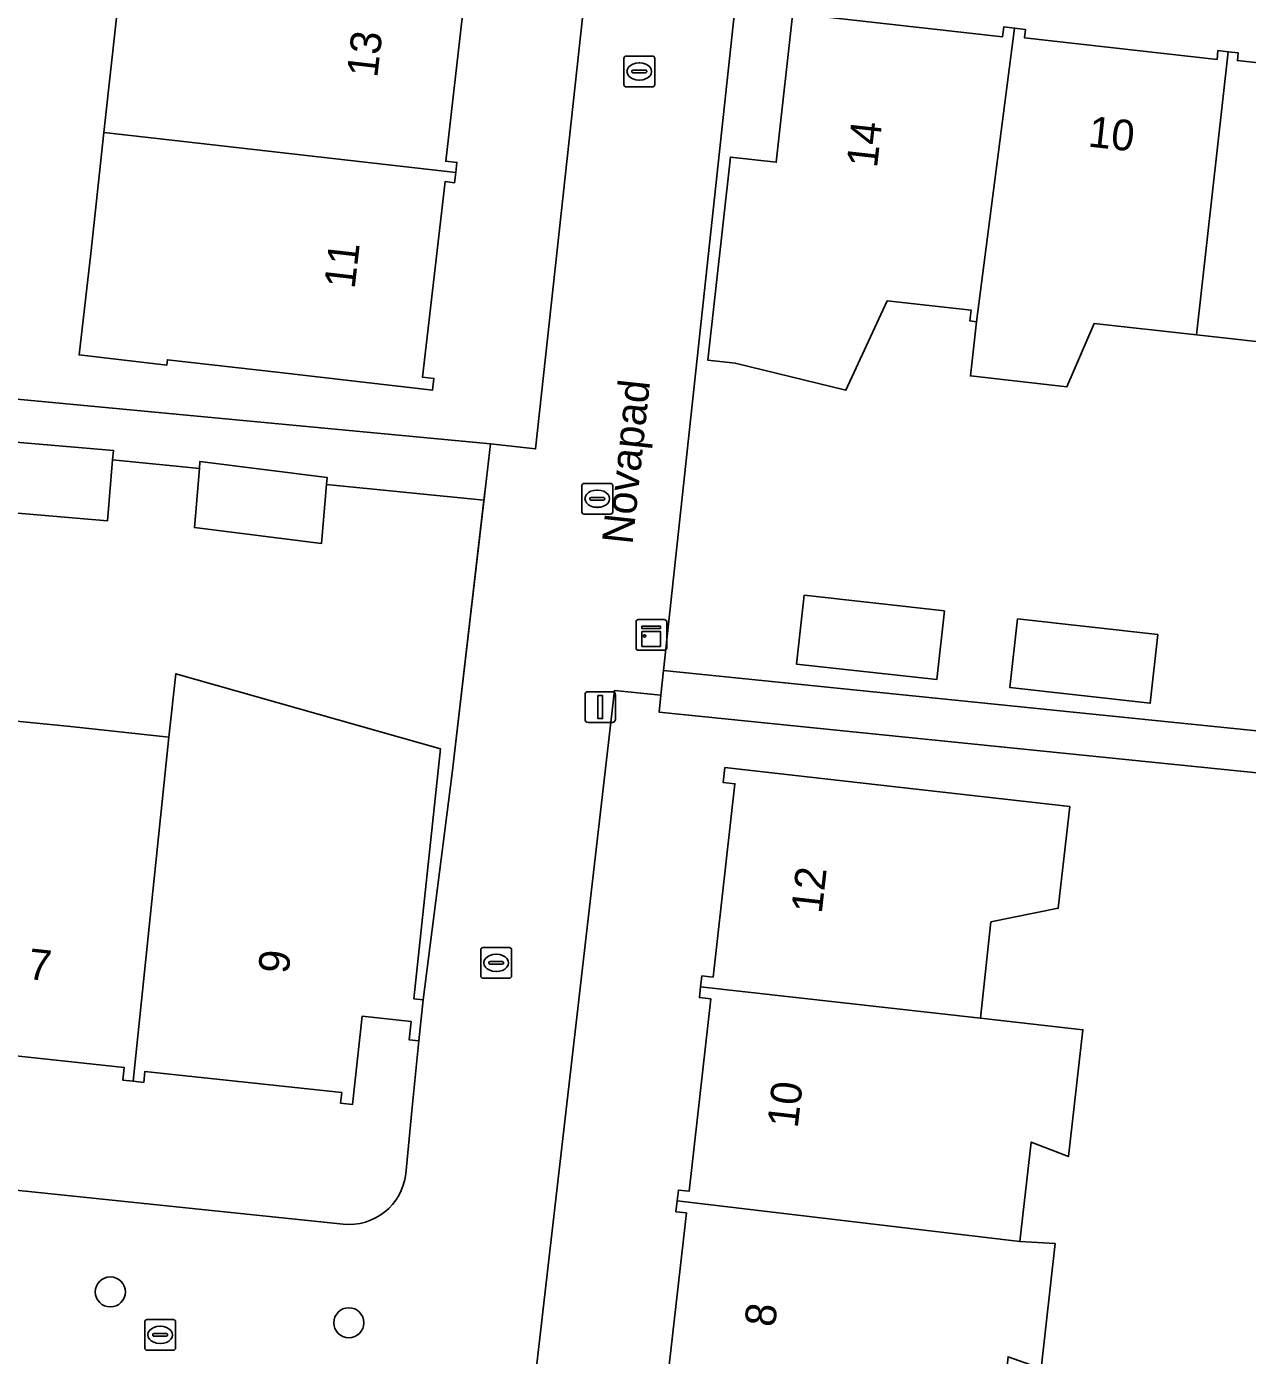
# Model space of a CAD drawing. Extents: x 162396 to 163643, y 386452 to 387406.
# Drawn here: x 162578.45 to 162618.15, y 386557.56 to 386600.76 of the extents above; entities that cross this region are included whole.
import ezdxf

# ---------------------------------------------------------------- set-up
doc = ezdxf.new("R2010")
doc.units = 0
for name, color, linetype in [('IMGEO_Boom', 7, 'Continuous'), ('IMGEO_Erf', 7, 'Continuous'), ('IMGEO_Kast', 7, 'Continuous'), ('IMGEO_Kolk', 7, 'Continuous'), ('IMGEO_Lichtmast', 7, 'Continuous'), ('IMGEO_Muur', 7, 'Continuous'), ('IMGEO_Openbare_ruimte_label', 7, 'Continuous'), ('IMGEO_Pand', 7, 'Continuous'), ('IMGEO_Pand_nummerreeks', 7, 'Continuous'), ('IMGEO_Rioolput', 7, 'Continuous'), ('IMGEO_Voetpad_open', 7, 'Continuous')]:
    doc.layers.add(name, color=color, linetype=linetype)

msp = doc.modelspace()

# ---------------------------------------------------------------- linework, layer by layer
at = {"layer": 'IMGEO_Boom'}
for centre in [(162581.176, 386559.622), (162588.931, 386558.618)]:
    msp.add_circle(centre, 0.489, dxfattribs=at)
at = {"layer": 'IMGEO_Erf'}
for points in [[(162596.17, 386613.523), (162573.621, 386621.455), (162572.865, 386612.427), (162575.967, 386612.081), (162575.162, 386604.868), (162572.06, 386605.214), (162571.791, 386602.773), (162574.014, 386602.603), (162573.55, 386598.243), (162573.516, 386597.92), (162571.284, 386598.158), (162571, 386595.578), (162573.194, 386595.411), (162572.861, 386591.042), (162572.731, 386589.343), (162570.462, 386589.516), (162570.75, 386593.304), (162570.318, 386589.379), (162593.535, 386587.193), (162595.004, 386587.03), (162597.635, 386611.189)], [(162602.317, 386609.066), (162599.162, 386579.822), (162624.637, 386577.233), (162625.902, 386585.912)], [(162592.802, 386602.656), (162592.083, 386596.383), (162592.447, 386596.342), (162592.409, 386596.012), (162592.371, 386595.684), (162592.058, 386595.72), (162591.329, 386589.36), (162591.696, 386589.318), (162591.652, 386588.94), (162586.685, 386589.509), (162583.03, 386589.927), (162583.01, 386589.755), (162580.161, 386590.082), (162580.539, 386593.381), (162580.97, 386597.316), (162581.379, 386601.045)], [(162603.802, 386601.141), (162610.188, 386600.428), (162610.224, 386600.747), (162610.578, 386600.708), (162610.932, 386600.668), (162610.901, 386600.391), (162617.16, 386599.692), (162617.191, 386599.977), (162617.52, 386599.94), (162617.85, 386599.903), (162617.822, 386599.654), (162624.139, 386598.948), (162624.166, 386599.196), (162624.462, 386599.163), (162623.798, 386593.216), (162626.682, 386592.894), (162627.944, 386602.131)], [(162625.902, 386585.912), (162623.003, 386586.236), (162623.182, 386587.839), (162619.865, 386588.21), (162619.6, 386590.388), (162616.491, 386590.735), (162613.161, 386591.107), (162612.279, 386589.05), (162609.139, 386589.401), (162609.336, 386591.165), (162609.127, 386591.188), (162609.166, 386591.536), (162606.433, 386591.841), (162605.086, 386588.936), (162601.493, 386589.817), (162600.599, 386589.916), (162601.336, 386596.515), (162602.826, 386596.349), (162603.402, 386601.507)], [(162576.254, 386578.363), (162579.886, 386578), (162583.082, 386577.656), (162583.303, 386579.717), (162591.915, 386577.274), (162591.043, 386569.15), (162591.351, 386569.116), (162592.294, 386576.49), (162593.323, 386585.365), (162588.204, 386585.869), (162588.042, 386583.95), (162583.908, 386584.471), (162583.94, 386584.851), (162584.071, 386586.392), (162581.251, 386586.674), (162581.084, 386584.694), (162576.633, 386585.071)], [(162621.065, 386555.69), (162618.776, 386555.914), (162619.21, 386560.374), (162621.499, 386560.15), (162621.836, 386562.28), (162619.504, 386562.535), (162620.011, 386567.17), (162622.027, 386566.95), (162622.267, 386568.894), (162620.254, 386569.106), (162620.743, 386573.743), (162622.81, 386573.525), (162623.054, 386576.032), (162599.022, 386578.467), (162599.075, 386579.017), (162597.565, 386579.171), (162594.088, 386549.01)], [(162599.206, 386556.003), (162599.906, 386562.187), (162599.565, 386562.226), (162599.605, 386562.578), (162599.645, 386562.931), (162599.993, 386562.892), (162600.701, 386569.146), (162600.328, 386569.188), (162600.368, 386569.542), (162600.409, 386569.897), (162600.772, 386569.856), (162601.484, 386576.143), (162601.105, 386576.186), (162601.159, 386576.67), (162606.128, 386576.108), (162612.372, 386575.401), (162611.998, 386572.094), (162609.807, 386571.651), (162609.465, 386568.517), (162612.797, 386568.142), (162612.33, 386564.02), (162611.119, 386564.493), (162610.753, 386561.263), (162611.899, 386561.193), (162611.439, 386557.132)], [(162590.782, 386563.457), (162590.984, 386565.511), (162591.207, 386567.783), (162590.898, 386567.816), (162590.962, 386568.412), (162589.361, 386568.583), (162589.053, 386565.719), (162588.661, 386565.761), (162588.698, 386566.103), (162582.3, 386566.791), (162582.261, 386566.434), (162581.92, 386566.471), (162581.578, 386566.508), (162581.623, 386566.921), (162575.474, 386567.581)], [(162550.761, 386565.77), (162588.742, 386561.821)]]:
    msp.add_lwpolyline(points, dxfattribs=at)
for points in [[(162608.296, 386581.765), (162608.047, 386579.528), (162603.485, 386580.035), (162603.734, 386582.272)], [(162615.238, 386580.997), (162614.989, 386578.76), (162610.427, 386579.267), (162610.676, 386581.504)]]:
    msp.add_lwpolyline(points, close=True, dxfattribs=at)
msp.add_arc((162588.934, 386563.671), 1.86, 264.0651, 353.3914, dxfattribs=at)
at = {"layer": 'IMGEO_Kast'}
for p, q in [((162598.268, 386580.556), (162598.268, 386581.397)), ((162598.268, 386581.397), (162598.268, 386580.556)), ((162598.343, 386581.481), (162599.184, 386581.481)), ((162599.184, 386581.481), (162598.343, 386581.481)), ((162599.268, 386581.406), (162599.268, 386580.565)), ((162599.268, 386580.565), (162599.268, 386581.406)), ((162599.193, 386580.481), (162598.352, 386580.481)), ((162598.352, 386580.481), (162599.193, 386580.481))]:
    msp.add_line(p, q, dxfattribs=at)
for points in [[(162598.463, 386581.271), (162599.063, 386581.271), (162599.063, 386581.186), (162598.463, 386581.186), (162598.463, 386581.271)], [(162598.463, 386581.096), (162599.063, 386581.096), (162599.063, 386580.607), (162598.463, 386580.607), (162598.463, 386581.096)]]:
    msp.add_lwpolyline(points, dxfattribs=at)
msp.add_circle((162598.547, 386580.945), 0.0377, dxfattribs=at)
for centre, start, end in [((162598.346, 386581.403), 92.4484, 184.2845), ((162598.346, 386581.403), 92.4484, 184.2845), ((162599.19, 386581.403), 2.4484, 94.2845), ((162599.19, 386581.403), 2.4484, 94.2845), ((162598.346, 386580.559), 182.4484, 274.2845), ((162598.346, 386580.559), 182.4484, 274.2845), ((162599.19, 386580.559), 272.4484, 4.2845), ((162599.19, 386580.559), 272.4484, 4.2845)]:
    msp.add_arc(centre, 0.0779, start, end, dxfattribs=at)
at = {"layer": 'IMGEO_Kolk'}
for p, q in [((162597.875, 386598.873), (162597.875, 386599.725)), ((162597.95, 386599.799), (162598.802, 386599.799)), ((162598.363, 386599.579), (162598.388, 386599.579)), ((162598.876, 386599.725), (162598.876, 386598.873)), ((162598.134, 386599.293), (162598.134, 386599.305)), ((162598.572, 386599.256), (162598.174, 386599.256)), ((162598.177, 386599.342), (162598.575, 386599.342)), ((162598.386, 386599.019), (162598.361, 386599.019)), ((162598.618, 386599.305), (162598.618, 386599.293)), ((162598.802, 386598.799), (162597.95, 386598.799)), ((162596.509, 386584.983), (162596.509, 386585.835)), ((162596.584, 386585.909), (162597.436, 386585.909)), ((162596.997, 386585.689), (162597.022, 386585.689)), ((162597.51, 386585.835), (162597.51, 386584.983)), ((162596.768, 386585.403), (162596.768, 386585.415)), ((162597.206, 386585.366), (162596.808, 386585.366)), ((162596.811, 386585.452), (162597.209, 386585.452)), ((162597.252, 386585.415), (162597.252, 386585.403)), ((162597.436, 386584.909), (162596.584, 386584.909)), ((162597.02, 386585.129), (162596.995, 386585.129)), ((162593.221, 386569.892), (162593.221, 386570.744)), ((162593.296, 386570.818), (162594.148, 386570.818)), ((162593.709, 386570.598), (162593.734, 386570.598)), ((162594.222, 386570.744), (162594.222, 386569.892)), ((162593.48, 386570.312), (162593.48, 386570.324)), ((162593.918, 386570.275), (162593.52, 386570.275)), ((162593.523, 386570.361), (162593.921, 386570.361)), ((162593.732, 386570.038), (162593.707, 386570.038)), ((162593.964, 386570.324), (162593.964, 386570.312)), ((162594.148, 386569.818), (162593.296, 386569.818))]:
    msp.add_line(p, q, dxfattribs=at)
for points in [[(162597.875, 386598.873), (162597.875, 386599.725)], [(162597.95, 386599.799), (162598.802, 386599.799)], [(162598.876, 386599.725), (162598.876, 386598.873)], [(162598.802, 386598.799), (162597.95, 386598.799)], [(162596.509, 386584.983), (162596.509, 386585.835)], [(162596.584, 386585.909), (162597.436, 386585.909)], [(162597.51, 386585.835), (162597.51, 386584.983)], [(162597.436, 386584.909), (162596.584, 386584.909)], [(162593.221, 386569.892), (162593.221, 386570.744)], [(162593.296, 386570.818), (162594.148, 386570.818)], [(162594.222, 386570.744), (162594.222, 386569.892)], [(162594.148, 386569.818), (162593.296, 386569.818)]]:
    msp.add_lwpolyline(points, dxfattribs=at)
for centre, radius, start, end in [((162597.952, 386599.723), 0.0765, 91.552, 178.448), ((162597.952, 386599.723), 0.0765, 91.552, 178.448), ((162598.8, 386599.723), 0.0765, 1.552, 88.448), ((162598.8, 386599.723), 0.0765, 1.552, 88.448), ((162598.174, 386599.302), 0.0403, 85.8775, 175.7526), ((162598.171, 386599.292), 0.0366, 178.938, 274.7102), ((162598.575, 386599.299), 0.043, 264.8664, 352.4533), ((162598.579, 386599.304), 0.0386, 1.7309, 96.639), ((162597.952, 386598.875), 0.0765, 181.552, 268.448), ((162597.952, 386598.875), 0.0765, 181.552, 268.448), ((162598.8, 386598.875), 0.0765, 271.552, 358.448), ((162598.8, 386598.875), 0.0765, 271.552, 358.448), ((162596.586, 386585.833), 0.0765, 91.552, 178.448), ((162596.586, 386585.833), 0.0765, 91.552, 178.448), ((162597.434, 386585.833), 0.0765, 1.552, 88.448), ((162597.434, 386585.833), 0.0765, 1.552, 88.448), ((162596.808, 386585.412), 0.0403, 85.8775, 175.7526), ((162596.805, 386585.402), 0.0366, 178.938, 274.7102), ((162597.209, 386585.409), 0.043, 264.8664, 352.4533), ((162597.213, 386585.414), 0.0386, 1.7309, 96.639), ((162596.586, 386584.985), 0.0765, 181.552, 268.448), ((162596.586, 386584.985), 0.0765, 181.552, 268.448), ((162597.434, 386584.985), 0.0765, 271.552, 358.448), ((162597.434, 386584.985), 0.0765, 271.552, 358.448), ((162593.298, 386570.742), 0.0765, 91.552, 178.448), ((162593.298, 386570.742), 0.0765, 91.552, 178.448), ((162594.146, 386570.742), 0.0765, 1.552, 88.448), ((162594.146, 386570.742), 0.0765, 1.552, 88.448), ((162593.52, 386570.321), 0.0403, 85.8775, 175.7526), ((162593.517, 386570.311), 0.0366, 178.938, 274.7102), ((162593.921, 386570.318), 0.043, 264.8664, 352.4533), ((162593.925, 386570.323), 0.0386, 1.7309, 96.639), ((162593.298, 386569.894), 0.0765, 181.552, 268.448), ((162593.298, 386569.894), 0.0765, 181.552, 268.448), ((162594.146, 386569.894), 0.0765, 271.552, 358.448), ((162594.146, 386569.894), 0.0765, 271.552, 358.448)]:
    msp.add_arc(centre, radius, start, end, dxfattribs=at)
for centre, major_axis, ratio, start_param, end_param in [((162598.362, 386599.299), (-0.387, 0.002), 0.722429, 4.712389, 7.853982), ((162598.387, 386599.299), (-0.39, 0.002), 0.717154, 1.570796, 4.712389), ((162596.996, 386585.409), (-0.387, 0.002), 0.722429, 4.712389, 7.853982), ((162597.021, 386585.409), (-0.39, 0.002), 0.717154, 1.570796, 4.712389), ((162593.708, 386570.318), (-0.387, 0.002), 0.722429, 4.712389, 7.853982), ((162593.733, 386570.318), (-0.39, 0.002), 0.717154, 1.570796, 4.712389)]:
    msp.add_ellipse(centre, major_axis=major_axis, ratio=ratio, start_param=start_param, end_param=end_param, dxfattribs=at)
at = {"layer": 'IMGEO_Lichtmast'}
for p, q in [((162596.711, 386579.134), (162597.501, 386579.134)), ((162597.501, 386579.134), (162596.711, 386579.134)), ((162596.611, 386578.234), (162596.611, 386579.034)), ((162596.611, 386579.034), (162596.611, 386578.234)), ((162597.601, 386579.034), (162597.601, 386578.234)), ((162597.601, 386578.234), (162597.601, 386579.034)), ((162597.501, 386578.134), (162596.711, 386578.134)), ((162596.711, 386578.134), (162597.501, 386578.134))]:
    msp.add_line(p, q, dxfattribs=at)
msp.add_lwpolyline([(162597.031, 386579.009), (162597.181, 386579.009), (162597.181, 386578.259), (162597.031, 386578.259), (162597.031, 386579.009)], dxfattribs=at)
for centre, start, end in [((162596.711, 386579.034), 90, 180), ((162596.711, 386579.034), 90, 180), ((162597.501, 386579.034), 0, 90), ((162597.501, 386579.034), 360, 90), ((162596.711, 386578.234), 180, 270), ((162596.711, 386578.234), 180, 270), ((162597.501, 386578.234), 270, 0), ((162597.501, 386578.234), 270, 0)]:
    msp.add_arc(centre, 0.1, start, end, dxfattribs=at)
at = {"layer": 'IMGEO_Muur'}
for points in [[(162593.372, 386585.788), (162592.294, 386576.49)], [(162591.207, 386567.783), (162590.984, 386565.511)]]:
    msp.add_lwpolyline(points, dxfattribs=at)
at = {"layer": 'IMGEO_Pand'}
for points in [[(162581.734, 386604.147), (162581.379, 386601.045), (162580.97, 386597.316), (162583.175, 386597.065), (162592.409, 386596.012), (162592.447, 386596.342), (162592.083, 386596.383), (162592.802, 386602.656), (162593.108, 386602.621), (162593.149, 386602.978), (162583.906, 386603.898)], [(162609.166, 386591.536), (162609.127, 386591.188), (162609.336, 386591.165), (162610.578, 386600.708), (162610.224, 386600.747), (162610.188, 386600.428), (162603.802, 386601.141), (162603.837, 386601.458), (162603.402, 386601.507), (162602.826, 386596.349), (162601.336, 386596.515), (162600.599, 386589.916), (162601.493, 386589.817), (162605.086, 386588.936), (162606.433, 386591.841)], [(162616.491, 386590.735), (162617.52, 386599.94), (162617.191, 386599.977), (162617.16, 386599.692), (162610.901, 386600.391), (162610.932, 386600.668), (162610.578, 386600.708), (162609.336, 386591.165), (162609.139, 386589.401), (162612.279, 386589.05), (162613.161, 386591.107)], [(162616.491, 386590.735), (162619.6, 386590.388), (162619.865, 386588.21), (162623.182, 386587.839), (162623.003, 386586.236), (162625.902, 386585.912), (162626.127, 386587.925), (162626.682, 386592.894), (162623.798, 386593.216), (162624.462, 386599.163), (162624.166, 386599.196), (162624.139, 386598.948), (162617.822, 386599.654), (162617.85, 386599.903), (162617.52, 386599.94)], [(162580.161, 386590.082), (162583.01, 386589.755), (162583.03, 386589.927), (162586.685, 386589.509), (162591.652, 386588.94), (162591.696, 386589.318), (162591.329, 386589.36), (162592.058, 386595.72), (162592.371, 386595.684), (162592.409, 386596.012), (162583.175, 386597.065), (162580.97, 386597.316), (162580.539, 386593.381)], [(162576.827, 386587.354), (162576.633, 386585.071), (162581.084, 386584.694), (162581.251, 386586.674), (162581.277, 386586.977)], [(162584.071, 386586.392), (162583.94, 386584.851), (162583.908, 386584.471), (162588.042, 386583.95), (162588.204, 386585.869), (162588.224, 386586.101), (162584.09, 386586.622)], [(162608.296, 386581.765), (162603.734, 386582.272), (162603.485, 386580.035), (162608.047, 386579.528)], [(162615.238, 386580.997), (162610.676, 386581.504), (162610.427, 386579.267), (162614.989, 386578.76)], [(162591.351, 386569.116), (162591.043, 386569.15), (162591.915, 386577.274), (162583.303, 386579.717), (162583.082, 386577.656), (162581.92, 386566.471), (162582.261, 386566.434), (162582.3, 386566.791), (162588.698, 386566.103), (162588.661, 386565.761), (162589.053, 386565.719), (162589.361, 386568.583), (162590.962, 386568.412), (162590.898, 386567.816), (162591.207, 386567.783)], [(162579.886, 386578), (162576.254, 386578.363), (162576.025, 386576.198), (162575.06, 386567.198), (162575.428, 386567.159), (162575.474, 386567.581), (162581.623, 386566.921), (162581.578, 386566.508), (162581.92, 386566.471), (162583.082, 386577.656)], [(162609.465, 386568.517), (162609.807, 386571.651), (162611.998, 386572.094), (162612.372, 386575.401), (162606.128, 386576.108), (162601.159, 386576.67), (162601.105, 386576.186), (162601.484, 386576.143), (162600.772, 386569.856), (162600.409, 386569.897), (162600.368, 386569.542)], [(162600.368, 386569.542), (162600.328, 386569.188), (162600.701, 386569.146), (162599.993, 386562.892), (162599.645, 386562.931), (162599.605, 386562.578), (162610.753, 386561.263), (162611.119, 386564.493), (162612.33, 386564.02), (162612.797, 386568.142), (162609.465, 386568.517)], [(162607.847, 386554.503), (162609.997, 386554.26), (162610.366, 386557.515), (162611.439, 386557.132), (162611.899, 386561.193), (162610.753, 386561.263), (162599.605, 386562.578), (162599.565, 386562.226), (162599.906, 386562.187), (162599.206, 386556.003), (162598.822, 386556.047), (162598.775, 386555.64)]]:
    msp.add_lwpolyline(points, close=True, dxfattribs=at)
at = {"layer": 'IMGEO_Rioolput'}
for p, q in [((162582.295, 386557.797), (162582.295, 386558.649)), ((162582.37, 386558.723), (162583.222, 386558.723)), ((162582.783, 386558.503), (162582.808, 386558.503)), ((162583.296, 386558.649), (162583.296, 386557.797)), ((162582.554, 386558.217), (162582.554, 386558.229)), ((162582.992, 386558.18), (162582.594, 386558.18)), ((162582.597, 386558.266), (162582.995, 386558.266)), ((162582.806, 386557.943), (162582.781, 386557.943)), ((162583.038, 386558.229), (162583.038, 386558.217)), ((162583.222, 386557.723), (162582.37, 386557.723))]:
    msp.add_line(p, q, dxfattribs=at)
for points in [[(162582.295, 386557.797), (162582.295, 386558.649)], [(162582.37, 386558.723), (162583.222, 386558.723)], [(162583.296, 386558.649), (162583.296, 386557.797)], [(162583.222, 386557.723), (162582.37, 386557.723)]]:
    msp.add_lwpolyline(points, dxfattribs=at)
for centre, radius, start, end in [((162582.372, 386558.647), 0.0765, 91.552, 178.448), ((162582.372, 386558.647), 0.0765, 91.552, 178.448), ((162583.22, 386558.647), 0.0765, 1.552, 88.448), ((162583.22, 386558.647), 0.0765, 1.552, 88.448), ((162582.594, 386558.226), 0.0403, 85.8775, 175.7526), ((162582.591, 386558.216), 0.0366, 178.938, 274.7102), ((162582.995, 386558.223), 0.043, 264.8664, 352.4533), ((162582.999, 386558.228), 0.0386, 1.7309, 96.639), ((162582.372, 386557.799), 0.0765, 181.552, 268.448), ((162582.372, 386557.799), 0.0765, 181.552, 268.448), ((162583.22, 386557.799), 0.0765, 271.552, 358.448), ((162583.22, 386557.799), 0.0765, 271.552, 358.448)]:
    msp.add_arc(centre, radius, start, end, dxfattribs=at)
for centre, major_axis, ratio, start_param, end_param in [((162582.782, 386558.223), (-0.387, 0.002), 0.722429, 4.712389, 7.853982), ((162582.807, 386558.223), (-0.39, 0.002), 0.717154, 1.570796, 4.712389)]:
    msp.add_ellipse(centre, major_axis=major_axis, ratio=ratio, start_param=start_param, end_param=end_param, dxfattribs=at)
at = {"layer": 'IMGEO_Voetpad_open'}
for points in [[(162597.635, 386611.189), (162595.004, 386587.03), (162593.535, 386587.193), (162593.372, 386585.788), (162593.323, 386585.365), (162592.294, 386576.49), (162591.351, 386569.116), (162591.207, 386567.783), (162590.984, 386565.511), (162590.782, 386563.457)], [(162594.088, 386549.01), (162597.565, 386579.171), (162599.075, 386579.017), (162599.162, 386579.822), (162602.317, 386609.066)], [(162576.827, 386587.354), (162581.277, 386586.977), (162581.251, 386586.674), (162584.071, 386586.392), (162584.09, 386586.622), (162588.224, 386586.101), (162588.204, 386585.869), (162593.323, 386585.365), (162593.372, 386585.788), (162593.535, 386587.193), (162570.318, 386589.379)], [(162588.742, 386561.821), (162550.761, 386565.77), (162549.978, 386565.851), (162550.287, 386568.543), (162527.318, 386571.051)]]:
    msp.add_lwpolyline(points, dxfattribs=at)
msp.add_lwpolyline([(162628.867, 386601.804), (162627.944, 386602.131), (162626.682, 386592.894), (162626.127, 386587.925), (162625.902, 386585.912), (162624.637, 386577.233), (162599.162, 386579.822), (162599.075, 386579.017), (162599.022, 386578.467), (162623.054, 386576.032), (162622.81, 386573.525), (162623.075, 386573.497), (162622.586, 386568.86), (162622.267, 386568.894), (162622.027, 386566.95), (162622.343, 386566.915), (162621.836, 386562.28), (162621.499, 386560.15), (162621.398, 386559.113), (162622.884, 386558.962), (162623.544, 386564.847), (162624.64, 386564.724)], close=True, dxfattribs=at)
msp.add_arc((162588.934, 386563.671), 1.86, 264.0651, 353.3914, dxfattribs=at)

# ---------------------------------------------------------------- texts
at = {"layer": 'IMGEO_Openbare_ruimte_label'}
msp.add_text('Novapad', height=1, rotation=83.856, dxfattribs=at).set_placement((162598.153, 386583.899))
at = {"layer": 'IMGEO_Pand_nummerreeks'}
for s, rotation, p in [('13', 83.4614, (162589.854, 386599.076)), ('10', 353.6277, (162612.939, 386596.863)), ('14', 83.6311, (162606.104, 386596.143)), ('11', 83.4611, (162589.118, 386592.209)), ('12', 83.5388, (162604.305, 386571.897)), ('7', 353.8105, (162578.465, 386569.798)), ('9', 83.8697, (162586.972, 386569.941)), ('10', 83.5412, (162603.524, 386564.923)), ('8', 83.5419, (162602.785, 386558.456))]:
    msp.add_text(s, height=1, rotation=rotation, dxfattribs=at).set_placement(p)

doc.saveas('drawing.dxf')
